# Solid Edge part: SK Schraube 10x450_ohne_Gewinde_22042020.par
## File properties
Author: fknapp
Template: Normal.par
Last saved by: fknapp
Revision: 35
Application: Solid Edge
Username: fknapp
Material: Aluminium
Genauigkeit: 0,99
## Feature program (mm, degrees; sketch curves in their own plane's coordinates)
sketch for "unnamed RevolvedProtrusion 1" plane through (0, 0, 0) normal (0, 0, 1) x-axis (1, 0, 0)
  line (0, 54) -> (9, 54)
  line (9, 54) -> (9, 53)
  line (9, 53) -> (5, 49)
  line (5, 49) -> (5, 46.3)
  line (5, 46.3) -> (4.7548, 46.3)
  arc centre (4.7548, 44.6952) radius 1.6048 from (4.7548, 46.3) to (3.15, 44.6952) ccw
  line (3.15, 44.6952) -> (3.15, 42)
  line (3.15, 42) -> (5, 42)
  line (5, -383) -> (5, 42)
  line (0.5, -396) -> (5, -383)
  line (0, -396) -> (0.5, -396)
revolve "unnamed RevolvedProtrusion 1" add full turn 360 deg about sketch line (0, 54) -> (0, -396)
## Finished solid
Body 1: solid body, 11 faces, 10 edges, 0 vertices.
  Faces by surface: cylinder 4, plane 4, cone 2, torus 1
  Edges by curve: circle 10
Bounding box of the edges (mm; curved faces can reach further): 18.000 x 450.000 x 18.000, from (-9, -396, -9) to (9, 54, 9).
Cylindrical faces by radius (mm): R3.15 x1, R5 x2, R9 x1
Conical faces (half-angle, radius in mm at the cone's reference point): 19.0935 deg R5 x1, 45 deg R9 x1
Toroidal faces (ring radius, tube radius in mm): R4.7548 r1.6048 x1
Planar faces by outward normal: +y 2, -y 2
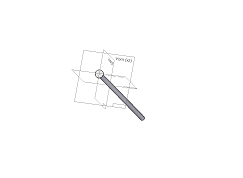
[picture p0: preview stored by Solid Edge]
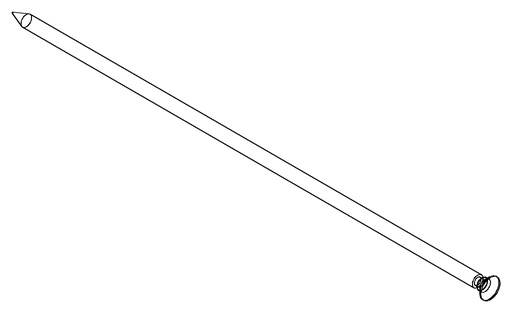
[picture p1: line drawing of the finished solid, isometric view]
